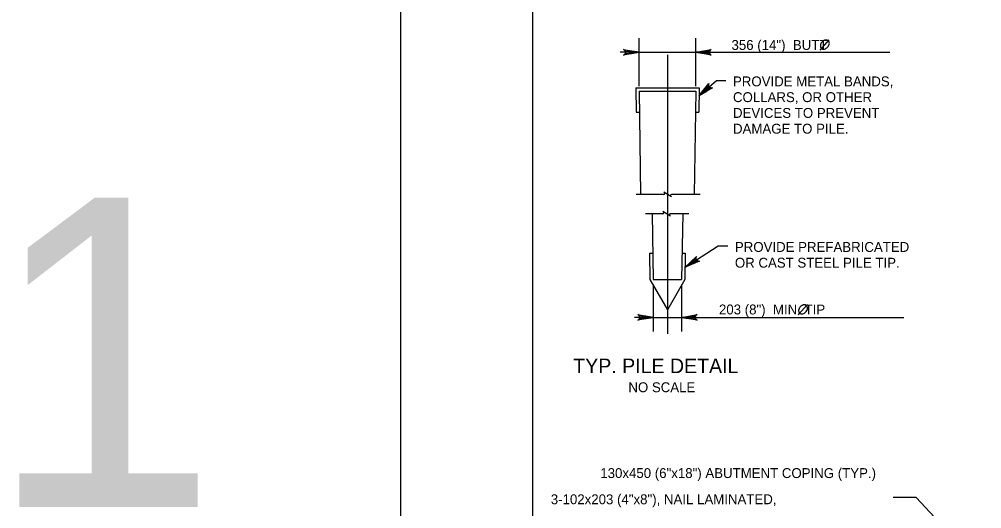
# Model space of a CAD drawing. Extents: x 635440 to 640306, y 296653 to 298484.
# Drawn here: x 638319.8 to 638611.5, y 298065.8 to 298214.2 of the extents above; entities that cross this region are included whole.
import ezdxf

# ---------------------------------------------------------------- set-up
doc = ezdxf.new("R2010")
doc.units = 0
for name, color, linetype in [('2', 7, 'Continuous'), ('4', 7, 'Continuous'), ('5', 7, 'Continuous'), ('53', 7, 'Continuous'), ('PLT-BNDY', 7, 'Continuous')]:
    doc.layers.add(name, color=color, linetype=linetype)

msp = doc.modelspace()

# ---------------------------------------------------------------- linework, layer by layer
at = {"layer": '2'}
msp.add_line((638475.46, 297856.46), (638475.46, 298420.46), dxfattribs=at)
at = {"layer": '4'}
for p, q in [((638516.22, 298203.48), (638516.22, 298118.82)), ((638506.61, 298193.47), (638506.72, 298186.08)), ((638506.61, 298193.47), (638525.84, 298193.47)), ((638507.61, 298192.49), (638508.1, 298161.11)), ((638507.61, 298192.49), (638524.84, 298192.49)), ((638524.84, 298192.49), (638524.35, 298161.11)), ((638525.84, 298193.47), (638525.73, 298186.08)), ((638506.72, 298186.08), (638507.71, 298186.08)), ((638524.74, 298186.08), (638525.73, 298186.08)), ((638515.13, 298161.11), (638506.75, 298161.11)), ((638517.43, 298160.39), (638515.12, 298161.84)), ((638526.11, 298161.11), (638517.46, 298161.11)), ((638514.81, 298155.27), (638509.53, 298155.27)), ((638511.6, 298155.27), (638511.91, 298135.3)), ((638517.12, 298154.54), (638514.81, 298156)), ((638522.71, 298155.27), (638517.15, 298155.27)), ((638520.85, 298155.27), (638520.53, 298135.3)), ((638510.83, 298143.34), (638510.93, 298135.29)), ((638510.83, 298143.34), (638511.82, 298143.34)), ((638520.63, 298143.34), (638521.61, 298143.34)), ((638521.61, 298143.34), (638521.52, 298135.29)), ((638510.93, 298135.29), (638516.22, 298126.12)), ((638511.91, 298135.3), (638520.53, 298135.3)), ((638521.52, 298135.29), (638516.22, 298126.12))]:
    msp.add_line(p, q, dxfattribs=at)
for centre, start, end in [((638515.09, 298161.45), 275.3286, 57.8672), ((638517.46, 298160.77), 90, 240), ((638514.78, 298155.61), 275.3286, 57.8672), ((638517.15, 298154.93), 90, 240)]:
    msp.add_arc(centre, 0.341, start, end, dxfattribs=at)
at = {"layer": '5'}
for p, q in [((638507.61, 298193.96), (638507.61, 298208.48)), ((638524.84, 298193.96), (638524.84, 298208.48)), ((638562.48, 298204.92), (638565.28, 298207.98)), ((638507.61, 298204.23), (638501.94, 298204.23)), ((638507.61, 298204.23), (638583.58, 298204.23)), ((638524.84, 298204.23), (638530.51, 298204.23)), ((638525.8, 298191.09), (638531.07, 298195.64)), ((638531.07, 298195.64), (638533.91, 298195.64)), ((638521.56, 298139.09), (638531.64, 298145.59)), ((638531.64, 298145.59), (638534.48, 298145.59)), ((638511.91, 298133.83), (638511.91, 298119.59)), ((638520.53, 298133.83), (638520.53, 298119.59)), ((638555.89, 298124.65), (638558.69, 298127.71)), ((638511.91, 298123.84), (638506.25, 298123.84)), ((638511.91, 298123.84), (638587.84, 298123.84)), ((638523.37, 298123.84), (638526.2, 298123.84)), ((638591.57, 298069.23), (638584.63, 298069.23))]:
    msp.add_line(p, q, dxfattribs=at)
for points in [[(638507.61, 298204.23), (638502.95, 298203.35), (638503.31, 298203.6), (638503.49, 298203.91), (638503.55, 298204.23), (638503.49, 298204.54), (638503.31, 298204.85), (638502.95, 298205.1), (638507.61, 298204.23), (638503.31, 298204.85), (638503.49, 298204.54), (638507.61, 298204.23), (638503.55, 298204.23), (638503.49, 298203.91), (638507.61, 298204.23), (638503.31, 298203.6)], [(638524.84, 298204.23), (638529.5, 298205.1), (638529.14, 298204.85), (638528.96, 298204.54), (638528.9, 298204.23), (638528.96, 298203.91), (638529.14, 298203.6), (638529.5, 298203.35), (638524.84, 298204.23), (638529.14, 298203.6), (638528.96, 298203.91), (638524.84, 298204.23), (638528.9, 298204.23), (638528.96, 298204.54), (638524.84, 298204.23), (638529.14, 298204.85)], [(638525.8, 298191.09), (638528.76, 298194.8), (638528.65, 298194.37), (638528.71, 298194.02), (638528.88, 298193.74), (638529.12, 298193.54), (638529.47, 298193.43), (638529.9, 298193.48), (638525.8, 298191.09), (638529.47, 298193.43), (638529.12, 298193.54), (638525.8, 298191.09), (638528.88, 298193.74), (638528.71, 298194.02), (638525.8, 298191.09), (638528.65, 298194.37)], [(638521.56, 298139.09), (638525.01, 298142.35), (638524.84, 298141.95), (638524.85, 298141.58), (638524.98, 298141.29), (638525.19, 298141.06), (638525.52, 298140.89), (638525.95, 298140.88), (638521.56, 298139.09), (638525.52, 298140.89), (638525.19, 298141.06), (638521.56, 298139.09), (638524.98, 298141.29), (638524.85, 298141.58), (638521.56, 298139.09), (638524.84, 298141.95)], [(638511.91, 298123.84), (638507.25, 298122.97), (638507.61, 298123.21), (638507.8, 298123.53), (638507.85, 298123.84), (638507.8, 298124.15), (638507.61, 298124.46), (638507.25, 298124.71), (638511.91, 298123.84), (638507.61, 298124.46), (638507.8, 298124.15), (638511.91, 298123.84), (638507.85, 298123.84), (638507.8, 298123.53), (638511.91, 298123.84), (638507.61, 298123.21)], [(638520.53, 298123.84), (638525.19, 298124.71), (638524.83, 298124.46), (638524.65, 298124.15), (638524.59, 298123.84), (638524.65, 298123.53), (638524.83, 298123.21), (638525.19, 298122.97), (638520.53, 298123.84), (638524.83, 298123.21), (638524.65, 298123.53), (638520.53, 298123.84), (638524.59, 298123.84), (638524.65, 298124.15), (638520.53, 298123.84), (638524.83, 298124.46)], [(638610.95, 298048.45), (638591.57, 298069.23)]]:
    msp.add_lwpolyline(points, dxfattribs=at)
for points in [[(638504.77, 298204.7), (638504.77, 298203.75), (638507.61, 298204.23)], [(638527.68, 298204.7), (638527.68, 298203.75), (638524.84, 298204.23)], [(638528.26, 298192.58), (638527.64, 298193.3), (638525.8, 298191.09)], [(638524.22, 298140.24), (638523.7, 298141.03), (638521.58, 298139.1)], [(638509.08, 298124.31), (638509.08, 298123.37), (638511.91, 298123.84)], [(638523.37, 298124.31), (638523.37, 298123.37), (638520.53, 298123.84)]]:
    msp.add_lwpolyline(points, close=True, dxfattribs=at)
for points in [[(638564.99, 298207.68), (638564.77, 298207.85), (638564.55, 298207.91), (638564.28, 298207.94), (638564.12, 298207.94), (638563.85, 298207.87), (638563.61, 298207.76), (638563.44, 298207.67), (638563.1, 298207.4), (638562.84, 298207.06), (638562.69, 298206.75), (638562.6, 298206.46), (638562.57, 298206.19), (638562.6, 298205.96), (638562.71, 298205.63), (638562.83, 298205.46), (638563.07, 298205.27), (638563.43, 298205.19), (638563.84, 298205.2), (638564.37, 298205.44), (638564.75, 298205.77), (638565.04, 298206.16), (638565.22, 298206.58), (638565.29, 298207.04), (638565.2, 298207.33), (638565, 298207.68)], [(638558.4, 298127.41), (638558.18, 298127.58), (638557.96, 298127.64), (638557.69, 298127.66), (638557.53, 298127.66), (638557.26, 298127.6), (638557.02, 298127.49), (638556.85, 298127.39), (638556.51, 298127.13), (638556.25, 298126.79), (638556.1, 298126.47), (638556.01, 298126.18), (638555.98, 298125.91), (638556.01, 298125.68), (638556.12, 298125.35), (638556.24, 298125.18), (638556.48, 298125), (638556.84, 298124.91), (638557.25, 298124.93), (638557.78, 298125.16), (638558.16, 298125.49), (638558.45, 298125.89), (638558.63, 298126.3), (638558.7, 298126.76), (638558.61, 298127.06), (638558.41, 298127.41)]]:
    msp.add_spline(points, degree=3, dxfattribs=at)
at = {"layer": 'PLT-BNDY'}
msp.add_lwpolyline([(638435.46, 298435.46), (639276.46, 298435.46), (639276.46, 297841.46), (638435.46, 297841.46)], close=True, dxfattribs=at)

# ---------------------------------------------------------------- texts
at = {"layer": '5'}
for s, height, p in [('356 (14")  BUTT', 3.0001, (638535.64, 298204.94)), ('PROVIDE METAL BANDS,', 3.0001, (638536.09, 298193.9)), ('COLLARS, OR OTHER ', 3.0001, (638536.09, 298189.12)), ('DEVICES TO PREVENT', 3.0001, (638536.09, 298184.34)), ('DAMAGE TO PILE.', 3.0001, (638536.09, 298179.56)), ('PROVIDE PREFABRICATED', 3.0001, (638536.67, 298143.7)), ('OR CAST STEEL PILE TIP.', 3.0001, (638536.67, 298138.92)), ('203 (8")  MIN. TIP', 3.0001, (638531.84, 298124.75)), ('TYP. PILE DETAIL', 4.4294, (638487.69, 298106.94)), ('NO SCALE', 3, (638504.39, 298101.17)), ('130x450 (6"x18") ABUTMENT COPING (TYP.)', 3.0001, (638495.88, 298075.14)), ('3-102x203 (4"x8"), NAIL LAMINATED,', 3.0001, (638480.88, 298067.2))]:
    msp.add_text(s, height=height, dxfattribs=at).set_placement(p)
at = {"layer": '53'}
msp.add_text('1', height=93.75, dxfattribs=at).set_placement((638310.24, 298066.39))

doc.saveas('drawing.dxf')
